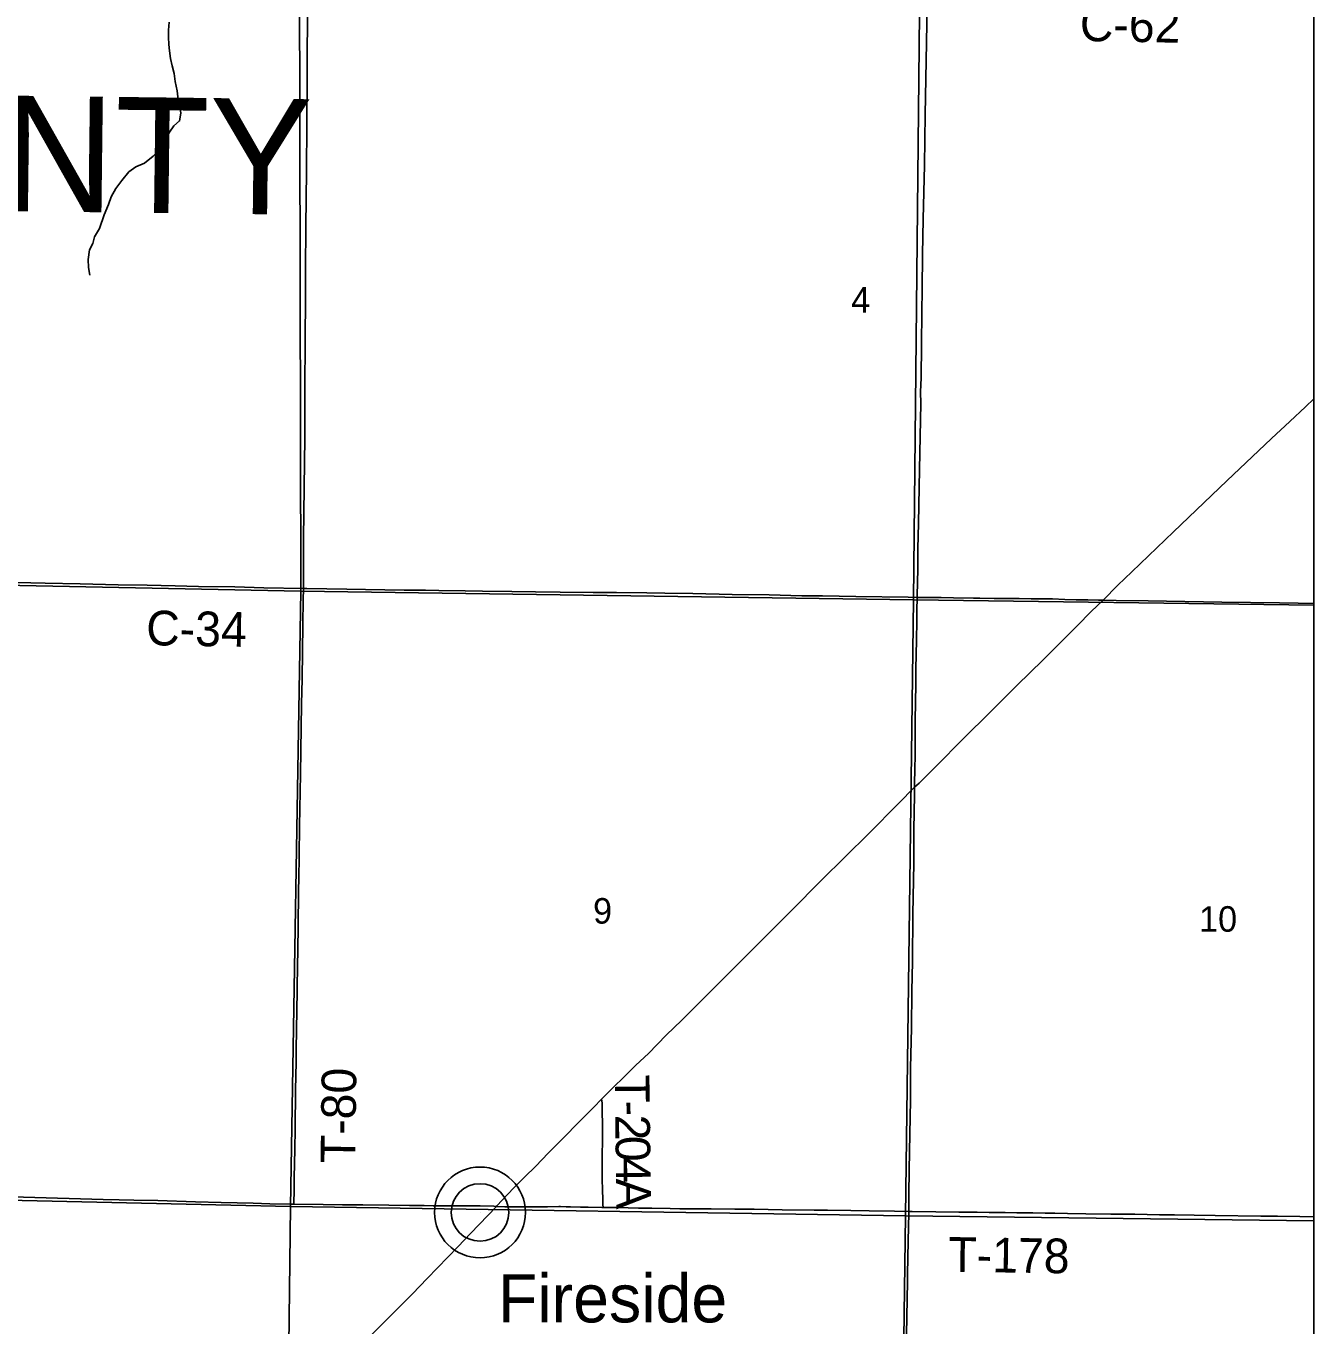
# Model space of a CAD drawing. Extents: x -8.5 to 18.7, y -20.3 to 7.
# Drawn here: x 14.521 to 18.741, y -15.303 to -11.043 of the extents above; entities that cross this region are included whole.
import ezdxf

# ---------------------------------------------------------------- set-up
doc = ezdxf.new("R2010")
doc.units = 0
for name, color, linetype in [('GM_X_Corporation', 7, 'Continuous'), ('GM_X_County_Road', 7, 'Continuous'), ('GM_X_County_Road_Text', 7, 'Continuous'), ('GM_X_County_Text', 7, 'Continuous'), ('GM_X_Minor_River', 7, 'Continuous'), ('GM_X_Section', 7, 'Continuous'), ('GM_X_Section_Text', 7, 'Continuous'), ('GM_X_State_Route', 7, 'Continuous'), ('GM_X_Township_Road', 7, 'Continuous'), ('GM_X_Township_Road_Text', 7, 'Continuous'), ('GM_X_Unincorporated', 7, 'Continuous'), ('GM_X_Unincorporated_Location', 7, 'Continuous'), ('GM_X_Unincorporated_Text', 7, 'Continuous'), ('SH_Cut_Line', 7, 'Continuous')]:
    doc.layers.add(name, color=color, linetype=linetype)

msp = doc.modelspace()

# ---------------------------------------------------------------- linework, layer by layer
at = {"layer": 'GM_X_Corporation'}
msp.add_lwpolyline([(11.2623, -20.262), (18.7413, -20.262), (18.7413, -10.9039)], dxfattribs=at)
at = {"layer": 'GM_X_County_Road'}
for points in [[(13.4246, -12.8443), (13.5551, -12.8466), (13.6956, -12.8496), (13.7938, -12.8517), (13.8758, -12.8535), (13.928, -12.8546), (13.979, -12.856), (14.0274, -12.857), (14.1368, -12.8587), (14.2686, -12.8621), (14.3978, -12.8649), (14.4898, -12.8669), (14.5831, -12.8685), (14.6986, -12.8712), (14.823, -12.8736), (14.9174, -12.8755), (15.0094, -12.8776), (15.0864, -12.879), (15.2046, -12.8811), (15.3002, -12.8835), (15.4297, -12.8859)], [(15.4297, -12.8859), (15.4407, -12.8861), (15.5725, -12.8887), (15.6334, -12.8894), (15.7602, -12.8914), (15.8297, -12.8919), (15.8733, -12.8921), (15.9602, -12.8937), (16.0161, -12.8948), (16.1131, -12.8956), (16.1901, -12.8969), (16.2709, -12.8977), (16.3791, -12.8991), (16.44, -12.8995), (16.456, -12.8994), (16.5552, -12.9), (16.6136, -12.9009), (16.7056, -12.9025), (16.8348, -12.9055), (16.9554, -12.9068), (17.0635, -12.9096), (17.1306, -12.9104), (17.24, -12.912), (17.4115, -12.9148), (17.4409, -12.9151)], [(17.4409, -12.9151), (17.5194, -12.9158), (17.56, -12.9166), (17.6254, -12.9173), (17.6464, -12.9176), (17.6935, -12.9188), (17.7381, -12.9194), (17.7753, -12.9194), (17.8146, -12.92), (17.8668, -12.9204), (17.8791, -12.9203), (17.884, -12.9201), (17.9248, -12.9222), (17.9621, -12.923), (18.0006, -12.9233), (18.0354, -12.9238), (18.0506, -12.9242)], [(18.0506, -12.9242), (18.0925, -12.9255), (18.1982, -12.927), (18.4394, -12.9305), (18.6283, -12.9333), (18.6893, -12.9339), (18.7413, -12.9348)]]:
    msp.add_lwpolyline(points, dxfattribs=at)
at = {"layer": 'GM_X_Minor_River'}
for points in [[(14.9896, -11.0302), (14.988, -11.0568), (14.9872, -11.0796), (14.9886, -11.1039), (14.9909, -11.1236), (14.9939, -11.1487), (14.9991, -11.173), (15.0059, -11.1988), (15.0096, -11.2246), (15.0164, -11.255), (15.0186, -11.2747), (15.0239, -11.2975), (15.0276, -11.3287), (15.0238, -11.3537), (15.0048, -11.3696), (14.9911, -11.3909), (14.9682, -11.4288), (14.9583, -11.4477), (14.9371, -11.4689), (14.9089, -11.4917), (14.8801, -11.5038), (14.858, -11.5204), (14.8345, -11.5492), (14.8154, -11.575), (14.8002, -11.6031), (14.7911, -11.6273), (14.7773, -11.662)], [(14.7773, -11.662), (14.7615, -11.7067), (14.7455, -11.7339), (14.7394, -11.7551), (14.7287, -11.7763), (14.724, -11.8082), (14.7254, -11.834), (14.7299, -11.8598)]]:
    msp.add_lwpolyline(points, dxfattribs=at)
at = {"layer": 'GM_X_Section'}
for points in [[(15.4166, -10.8695), (15.4394, -10.8699), (17.4495, -10.8937), (17.4286, -12.923), (15.4216, -12.8944)], [(13.4153, -12.8545), (15.4216, -12.8944), (15.3877, -14.9113), (13.3845, -14.866)], [(15.4216, -12.8944), (17.4286, -12.923), (17.403, -14.9422), (15.3877, -14.9113)], [(13.3845, -14.866), (15.3877, -14.9113), (15.3636, -16.9183), (13.3536, -16.8784)], [(15.3877, -14.9113), (17.403, -14.9422), (17.3759, -16.9531), (15.3636, -16.9183)]]:
    msp.add_lwpolyline(points, close=True, dxfattribs=at)
at = {"layer": 'GM_X_State_Route'}
msp.add_lwpolyline([(15.6454, -15.3394), (15.7291, -15.2557), (15.7867, -15.1973), (15.8352, -15.1473), (15.9364, -15.0429), (15.9773, -14.9994), (16.0619, -14.9109), (16.0639, -14.9088), (16.1186, -14.8514), (16.1554, -14.8139), (16.1897, -14.7797), (16.2332, -14.7352), (16.3813, -14.586), (16.4069, -14.5601), (16.5192, -14.4486), (16.5601, -14.4102), (16.6186, -14.3503), (16.6699, -14.3005), (16.8485, -14.1211), (16.9534, -14.0162), (17.0269, -13.9434), (17.1273, -13.8417), (17.282, -13.6885), (17.3794, -13.5903), (17.4324, -13.5374), (17.447, -13.5236), (17.5134, -13.458), (17.5822, -13.3887), (17.6907, -13.2806), (17.768, -13.2041), (17.8533, -13.1197), (17.9651, -13.0084), (18.0112, -12.962), (18.0506, -12.9242), (18.098, -12.8754), (18.1439, -12.831), (18.2266, -12.7525), (18.2808, -12.7004), (18.4553, -12.5338), (18.602, -12.3944), (18.662, -12.3389), (18.7135, -12.291), (18.7413, -12.2645)], dxfattribs=at)
at = {"layer": 'GM_X_Township_Road'}
for points in [[(15.4297, -12.8859), (15.4298, -12.8794), (15.43, -12.8197), (15.4305, -12.7226), (15.433, -12.4717), (15.4343, -12.3948), (15.4343, -12.3097), (15.4342, -12.2456), (15.4354, -12.0601), (15.4361, -11.9456), (15.4369, -11.8421), (15.4381, -11.6993), (15.4393, -11.5181), (15.4415, -11.2131), (15.4425, -11.1165), (15.4427, -11.0431), (15.4435, -10.9338), (15.4444, -10.8817), (15.4443, -10.875), (15.4442, -10.8681)], [(17.4409, -12.9151), (17.441, -12.9094), (17.4428, -12.8222), (17.4434, -12.7562), (17.4456, -12.6718), (17.4487, -12.4965), (17.4527, -12.2802), (17.4522, -12.2415), (17.4537, -12.1957), (17.4547, -12.0871), (17.4562, -11.98), (17.4571, -11.9062), (17.4586, -11.7917), (17.4603, -11.6762), (17.4645, -11.4983), (17.4672, -11.333), (17.4701, -11.1573), (17.4736, -10.9743), (17.4739, -10.9356), (17.4745, -10.8982), (17.4746, -10.8905)], [(15.3984, -14.9042), (15.3987, -14.8928), (15.3992, -14.8654), (15.3998, -14.817), (15.4014, -14.7239), (15.4023, -14.6578), (15.4042, -14.5298), (15.4056, -14.4367), (15.4062, -14.3969), (15.4069, -14.3322), (15.4089, -14.2047), (15.4094, -14.1748), (15.4101, -14.142), (15.4101, -14.1138), (15.4109, -14.0804), (15.4124, -13.9833), (15.4129, -13.9558), (15.4132, -13.9172), (15.4141, -13.8711), (15.4142, -13.8395), (15.4153, -13.7606), (15.4171, -13.665), (15.4196, -13.4947), (15.4239, -13.2635), (15.4251, -13.1827), (15.4279, -13.0025), (15.4292, -12.9242), (15.4297, -12.8859)], [(17.4324, -13.5374), (17.4327, -13.5218), (17.4332, -13.4818), (17.4342, -13.4287), (17.4347, -13.3175), (17.4366, -13.2008), (17.4369, -13.1673), (17.4368, -13.149), (17.439, -13.0558), (17.4393, -12.9921), (17.4398, -12.9583), (17.4409, -12.9151)], [(17.4136, -14.9277), (17.4141, -14.8729), (17.4152, -14.7908), (17.4166, -14.6746), (17.4188, -14.5633), (17.4195, -14.4579), (17.4221, -14.3259), (17.4235, -14.2053), (17.4251, -14.1083), (17.4266, -13.9529), (17.4289, -13.8423), (17.4298, -13.7864), (17.4305, -13.6763), (17.4322, -13.5633), (17.4324, -13.5374)], [(16.4115, -14.9144), (16.4112, -14.9043), (16.4108, -14.8884), (16.4098, -14.8564), (16.4092, -14.8213), (16.4091, -14.7765), (16.4095, -14.661), (16.4092, -14.5813), (16.4082, -14.5712), (16.4069, -14.5601)], [(13.3905, -14.8568), (13.4613, -14.858), (13.5471, -14.8599), (13.6987, -14.8634), (13.8155, -14.8656), (13.9597, -14.8687), (14.0306, -14.8703), (14.2792, -14.8756), (14.36, -14.8771), (14.5129, -14.881), (14.7739, -14.8883), (14.8261, -14.889), (14.8745, -14.8903), (14.9528, -14.8921), (15.0758, -14.8957), (15.1604, -14.8977), (15.2648, -14.9003), (15.3194, -14.9022), (15.389, -14.9041), (15.3984, -14.9042)], [(15.3984, -14.9042), (15.4947, -14.9052), (15.5581, -14.9057), (15.624, -14.9064), (15.7098, -14.907), (15.7768, -14.9077), (15.8253, -14.9085), (15.8551, -14.9092), (15.8787, -14.909), (15.9084, -14.9095), (15.9642, -14.9093), (16.0088, -14.9089), (16.0534, -14.9104), (16.0619, -14.9109)], [(16.0619, -14.9109), (16.0895, -14.9123), (16.1653, -14.9124), (16.2299, -14.9119), (16.2671, -14.9116), (16.272, -14.9118), (16.2904, -14.9123), (16.305, -14.9124), (16.3374, -14.9134), (16.3496, -14.9136), (16.3632, -14.9139), (16.4076, -14.9144), (16.4115, -14.9144)], [(16.4115, -14.9144), (16.4309, -14.9144), (16.4643, -14.915), (16.4766, -14.9151), (16.494, -14.9155), (16.5275, -14.9164), (16.5486, -14.9169), (16.571, -14.9171), (16.6319, -14.9178), (16.6629, -14.9185), (16.74, -14.9189), (16.7661, -14.919), (16.8432, -14.9202), (16.9066, -14.9205), (16.9986, -14.9219), (17.103, -14.9228), (17.1473, -14.9237), (17.2231, -14.9245), (17.284, -14.9257), (17.3661, -14.9265), (17.4136, -14.9277)], [(17.4049, -15.3898), (17.4068, -15.2734), (17.4091, -15.1569), (17.409, -15.1332), (17.411, -15.0244), (17.4136, -14.932), (17.4136, -14.9277)], [(17.4136, -14.9277), (17.4245, -14.9279), (17.5016, -14.9288), (17.5774, -14.9295), (17.606, -14.9295), (17.6209, -14.9295), (17.637, -14.9297), (17.6767, -14.9305), (17.6878, -14.9308), (17.7288, -14.9313), (17.7673, -14.932), (17.8196, -14.9326), (17.8606, -14.9332), (17.8916, -14.9337), (17.9339, -14.9344), (17.9936, -14.935), (18.0756, -14.936), (18.1539, -14.9369), (18.2347, -14.9384), (18.2844, -14.9389), (18.3491, -14.94), (18.4175, -14.9403), (18.5666, -14.9428), (18.6214, -14.9434), (18.6947, -14.944), (18.7413, -14.9448)]]:
    msp.add_lwpolyline(points, dxfattribs=at)
at = {"layer": 'GM_X_Unincorporated'}
for radius in [0.1488, 0.0943]:
    msp.add_circle((16.0084, -14.9309), radius, dxfattribs=at)
at = {"layer": 'GM_X_Unincorporated_Location'}
msp.add_line((16.0084, -14.9309), (16.0084, -14.9309), dxfattribs=at)
at = {"layer": 'GM_X_Unincorporated_Text'}
for points in [[(18.7413, -12.9406), (18.7413, -10.9121), (17.4495, -10.8937), (17.4286, -12.923)], [(18.7413, -14.9582), (18.7413, -12.9406), (17.4286, -12.923), (17.403, -14.9422)], [(18.7413, -16.9689), (18.7413, -14.9582), (17.403, -14.9422), (17.3759, -16.9531)]]:
    msp.add_lwpolyline(points, close=True, dxfattribs=at)
at = {"layer": 'SH_Cut_Line'}
msp.add_lwpolyline([(-8.4587, -10.6981), (-8.4587, -20.262), (18.7413, -20.262), (18.7413, -10.9039)], dxfattribs=at)

# ---------------------------------------------------------------- texts
at = {"layer": 'GM_X_County_Road_Text'}
for s, rotation, p in [('C-62', 358.9703, (17.9733, -11.0918)), ('C-34', 358.9645, (14.9138, -13.0717))]:
    msp.add_text(s, height=0.11364, rotation=rotation, dxfattribs=at).set_placement(p)
at = {"layer": 'GM_X_County_Text'}
msp.add_text('SENECA COUNTY', height=0.378788, rotation=359.3047, dxfattribs=at).set_placement((11.0943, -11.6087))
at = {"layer": 'GM_X_Section_Text'}
for s, height, p in [('4', 0.0837, (17.2248, -11.982)), ('9', 0.0837, (16.379, -13.9843)), ('10', 0.08371, (18.3648, -14.0109))]:
    msp.add_text(s, height=height, rotation=0, dxfattribs=at).set_placement(p)
at = {"layer": 'GM_X_Township_Road_Text'}
for s, height, rotation, p in [('T-80', 0.11364, 89.2905, (15.5995, -14.7698)), ('T', 0.1136, 270.681, (16.4498, -14.4799)), ('-', 0.1136, 270.681, (16.4508, -14.5647)), ('2', 0.1136, 270.681, (16.4514, -14.6109)), ('0', 0.1136, 270.6813, (16.4522, -14.6804)), ('4', 0.1136, 270.6882, (16.453, -14.7498)), ('A', 0.1136, 270.9438, (16.4539, -14.8198)), ('T-178', 0.11364, 359.1693, (17.5426, -15.1249))]:
    msp.add_text(s, height=height, rotation=rotation, dxfattribs=at).set_placement(p)
at = {"layer": 'GM_X_Unincorporated_Text'}
msp.add_text('Fireside', height=0.15795, rotation=0, dxfattribs=at).set_placement((16.0673, -15.2911))

doc.saveas('drawing.dxf')
